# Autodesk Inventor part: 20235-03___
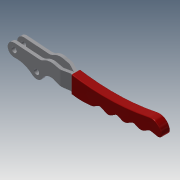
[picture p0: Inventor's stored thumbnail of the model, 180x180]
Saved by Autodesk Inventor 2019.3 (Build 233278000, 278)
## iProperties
Created: 2010-06
Part Number: 20235-03___
Material: Ogólny
Document SubType Name: Modeling
Designer: CADENGINEERING4
Density: 1 g/cm^3
Appearance: Domyślna
Author: CADENGINEERING4
Revision Number: ANY
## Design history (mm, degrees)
feature "NONE"
node "Bryła1"
